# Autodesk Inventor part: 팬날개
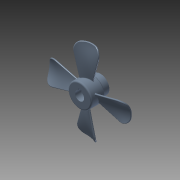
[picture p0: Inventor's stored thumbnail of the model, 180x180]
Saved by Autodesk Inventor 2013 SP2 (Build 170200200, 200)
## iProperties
Company: 한국ATC센터
Created: 2016-06
Part Number: 팬날개
Document SubType Name: Modeling
Designer: mdu
Density: 1.493 g/cm^3
Material: ABS 플라스틱
Mass: 1497.56 g
Surface Area: 466.268 cm^2
Volume: 190.529 cm^3
Author: mdu
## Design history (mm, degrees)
sketch "스케치1"
  geometry: L1 (-15, 0)-(15, 0); L2 (-15, 0)-(-15, 17); L3 (-15, 17)-(5, 17); L4 (5, 17)-(5, 13); L5 (5, 13)-(15, 13); L6 (15, 13)-(15, 0); 2 further points
  constraints: 12 end point, 3 parallel, 2 perpendicular, 1 coincident, 1 horizontal, 1 midpoint
  dimensions: "d0" = 30 distance of L1.start L1.end; "d8" = 34 diameter of L3 L1; "d10" = 26 diameter of L5 L1; "d32" = 20 distance of L2.end L3.end
revolve "회전1" sketch "스케치1" stored, may be unused: angle "d11" = 90 deg
node "작업 평면2"
sketch "스케치7"
  geometry: L1 (-15, 17)-(5, 17) reference; L2 (-15, -17)-(5, -17) reference; L3 (-5, 17)-(-5, -17); A1 r 35 centre (-36.399, -13.457) between (-2, -7) and (-8, 7); 1 further point
  constraints: 2 end point, 2 midpoint, 2 point on circle, 1 centre point
  dimensions: "d36" = 35 radius of A1; "d37" = 10 distance from line of A1.start L2; "d38" = 10 distance from line of A1.end L1; "d45" = 3 distance from line of A1.end L3; "d46" = 3 distance from line of A1.start L3
sketch "3D 스케치1"
  geometry: L1 through (0, 0) direction (1, 0) reference; L2 through (0, 0) direction (1, 0) reference; 13 other entities
  constraints: 2 collinear
  node "투영 원본 위치 스케치7"
sketch "스케치8"
  geometry: L1 (-15, 17)-(5, 17) reference; L2 (-15, -17)-(5, -17) reference; L3 (-5, 17)-(-5, -17); A1 r 30 centre (-28.74, -3.591) between (-3, -19) and (-9, 19); 1 further point
  constraints: 2 end point, 2 midpoint, 2 point on circle, 1 centre point
  dimensions: "d43" = 30 radius of A1; "d47" = 4 distance from line of A1.end L3; "d48" = 2 distance from line of A1.start L3; "d58" = 2 distance from line of A1.end L1; "d59" = 2 distance from line of A1.start L2
sketch "3D 스케치2"
sketch "3D 스케치3"
feature "경계 패치1" sketch "3D 스케치2", "3D 스케치3" dims "d50" = 0
feature "연장1" dims "d55" = 2
feature "두껍게 하기1" dims "d51" = 2, "d52" = 2
sketch "스케치9"
  geometry: C1 r 59 at (0, 0); 1 further point
  constraints: 1 centre point, 1 coincident
  dimensions: "d60" = 118 diameter of C1
extrude "돌출2" sketch "스케치9" distance "d62" = 200; taper "d63" = 0 deg
fillet "모깎기6" dims "d64" = 10
fillet "모깎기7" dims "d66" = 0.8
fillet "모깎기8" dims "d67" = 0.8
sketch "스케치2"
  geometry: L1 (-2.5, 6)-(-2.5, 8.8); L2 (-2.5, 8.8)-(2.5, 8.8); L3 (2.5, 8.8)-(2.5, 6); A1 r 6.5 centre (0, 0) between (-2.5, 6) and (2.5, 6); 1 further point
  constraints: 6 end point, 2 parallel, 2 point on circle, 1 centre point, 1 coincident, 1 horizontal, 1 vertical
  dimensions: "d12" = 13 diameter of A1; "d13" = 5 distance of L1.end L2.end; "d14" = 15.3 dimension on A1 L2 (computed from d12)
extrude "돌출1" cut sketch "스케치2" stored distance "d15" = 10; taper "d16" = 0 deg
chamfer "모따기1" distance "d17" = 1; stored, may be unused: second distance "d18" = 2, angle "d19" = 45 deg
node "작업 평면1"
sketch "스케치3"
  geometry: L1 (5, -13)-(5, 13) reference; 3 further points
  constraints: 1 horizontal alignment, 1 midpoint
  dimensions: "d20" = 5 distance from line of L1 point (0, 0)
hole "구멍1" sketch "스케치3" at (0, 0) diameter "d21" = 3.242; stored, may be unused: countersink angle "d25" = 90 deg, drill point angle "d27" = 118 deg; dims "d22" = 6, "d23" = 4, "d24" = 2, "d26" = 8
fillet "모깎기9" dims "d77" = 2
fillet "모깎기10" dims "d78" = 2
fillet "모깎기11" dims "d79" = 2
node "솔리드1"
pattern_circular "원형 패턴1" dims "d69" = 360 deg
pattern_circular "원형 패턴2" dims angle "d72" = 360 deg
pattern_circular "원형 패턴3" dims angle "d75" = 360 deg
node "투영 원본 위치 스케치8"
node "곡면1"
node "곡면2"
node "곡면3"
node "곡면4"
feature "경계 패치2"
feature "경계 패치3"
feature "경계 패치4"
